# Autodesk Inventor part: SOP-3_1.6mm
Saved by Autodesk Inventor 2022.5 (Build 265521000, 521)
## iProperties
Created: 2024-12
Part Number: SOP-3_1.6mm
Material: Generic
Document SubType Name: Modeling
Designer: AdminForWorker
Density: 1 g/cm^3
Appearance: Default
Title: SOP-3_1.6mm
Author: AdminForWorker
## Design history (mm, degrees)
feature "Body1" [lead]
feature "lead2"
feature "lead1"
feature "lead3"
body "Solid1"
body "Solid2"
body "Solid3"
body "Solid4"
